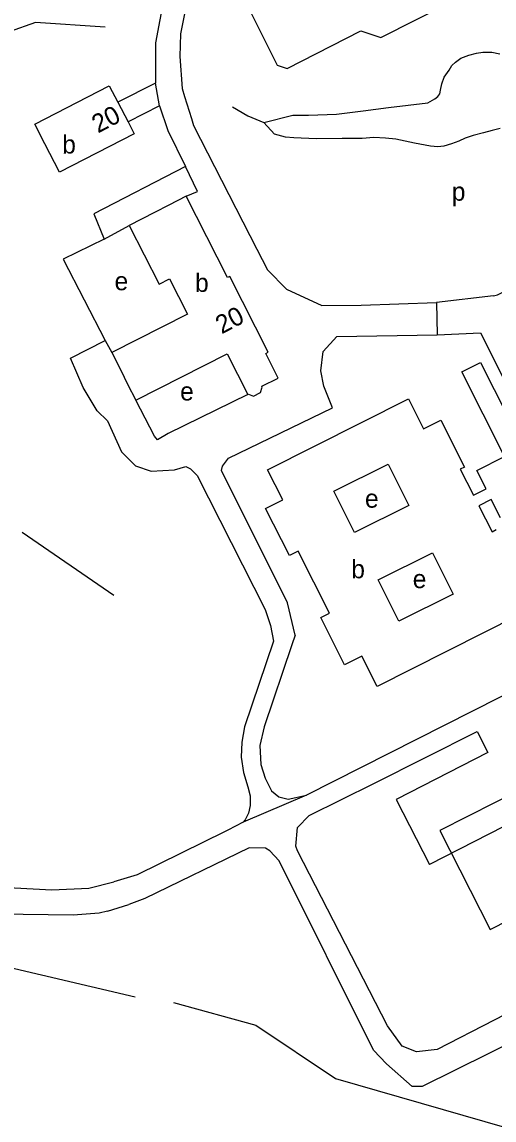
# Model space of a CAD drawing. Extents: x 158142 to 159655, y 385262 to 387204.
# Drawn here: x 158802.8 to 158905.5, y 386164.4 to 386403.5 of the extents above; entities that cross this region are included whole.
import ezdxf

# ---------------------------------------------------------------- set-up
doc = ezdxf.new("R2010")
doc.units = 0
for name, color, linetype in [('BLT_Basislijn', 7, 'Continuous'), ('BLT_Bebouwing', 7, 'Continuous'), ('BLT_Centroide', 7, 'Continuous'), ('BLT_Huisnummer', 7, 'Continuous'), ('BLT_Plantopo', 7, 'Continuous'), ('BLT_Vlakafsluiter', 7, 'Continuous')]:
    doc.layers.add(name, color=color, linetype=linetype)

msp = doc.modelspace()

# ---------------------------------------------------------------- linework, layer by layer
at = {"layer": 'BLT_Basislijn'}
for p, q in [((158851.89, 386406.97), (158858.34, 386394.06)), ((158831.88, 386390.19), (158823.68, 386386.01)), ((158832.78, 386385.23), (158831.88, 386390.19)), ((158838.18, 386387.27), (158839.69, 386382.43)), ((158832.78, 386385.23), (158825.9, 386381.7)), ((158820.68, 386356.19), (158826.18, 386359.19)), ((158820.95, 386334.15), (158822.37, 386331.49)), ((158819.17, 386318.8), (158816.15, 386323.91)), ((158802.88, 386292.41), (158822.8, 386278.65)), ((158862.25, 386269.97), (158861.53, 386267.84)), ((158857.51, 386268.65), (158851.23, 386250)), ((158861.53, 386267.84), (158855.51, 386250)), ((158901.79, 386248.97), (158904.15, 386244.37)), ((158904.15, 386244.37), (158884.21, 386234.14)), ((158934.79, 386242.24), (158891.45, 386220.02)), ((158864.7, 386235.1), (158850.97, 386229.24)), ((158884.21, 386234.14), (158891.45, 386220.02)), ((158850.97, 386229.24), (158847.58, 386227.51)), ((158821.41, 386209.88), (158826.08, 386211.28)), ((158784, 386201.42), (158827.48, 386191.22))]:
    msp.add_line(p, q, dxfattribs=at)
for points in [[(158858.34, 386394.06), (158860.47, 386393.36), (158876.54, 386401.57), (158880.9, 386400.07), (158949.09, 386434.63)], [(158843.29, 386430.77), (158837.33, 386400.92), (158837.2, 386395.94), (158837.65, 386388.99), (158838.18, 386387.27)], [(158836.62, 386424.04), (158831.91, 386398.97), (158831.88, 386390.19)], [(158820.92, 386402.37), (158805.76, 386403.38), (158800.05, 386401.35), (158789.96, 386389.69), (158788.28, 386379.99), (158783.8, 386372.81), (158785.38, 386364.31), (158786.18, 386360.05), (158771.15, 386323.25)], [(158906.8, 386380.3), (158905.07, 386379.85), (158903.18, 386379.34), (158900.98, 386378.79), (158899.22, 386378.16), (158897.83, 386377.53), (158896.22, 386376.92), (158894.54, 386376.46), (158893.24, 386376.27), (158891.64, 386376.41), (158888.2, 386377.1), (158884.11, 386377.96), (158881.92, 386378.2), (158879.37, 386378.33), (158876.8, 386378.14), (158872.5, 386378.08), (158866.83, 386378.01), (158861.94, 386378.24), (158860.14, 386378.41), (158857.76, 386379.05), (158855.42, 386381.62), (158861.72, 386383.19), (158865.15, 386383.21), (158871.2, 386383.4), (158877.05, 386384.1), (158882.55, 386384.87), (158891.06, 386385.9), (158892.59, 386386.73), (158893.28, 386387.27), (158893.68, 386387.84), (158893.85, 386388.62), (158894.16, 386390.03), (158894.66, 386391.44), (158895.73, 386393.02), (158896.32, 386393.97), (158897.14, 386394.75), (158898.3, 386395.59), (158900.01, 386396.24), (158901.67, 386396.68), (158903.06, 386396.92), (158904.98, 386396.94), (158906.76, 386396.58)], [(158905.37, 386343.81), (158906.21, 386344.08), (158977.73, 386380.2), (158991.61, 386387.46), (159005.32, 386393.92)], [(158832.78, 386385.23), (158834.58, 386379.83), (158838.41, 386372.01)], [(158848.62, 386384.98), (158851.98, 386383.07), (158855.42, 386381.62)], [(158839.69, 386382.43), (158840.15, 386380.94), (158853.91, 386354.02)], [(158838.41, 386372.01), (158818.43, 386361.7), (158820.68, 386356.19)], [(158838.56, 386365.53), (158841, 386366.54), (158838.41, 386372.01)], [(158820.68, 386356.19), (158811.79, 386351.81), (158820.95, 386334.15)], [(158853.91, 386354.02), (158856.22, 386349.54), (158860.35, 386345.29), (158868.06, 386341.71), (158876.57, 386341.82), (158892.95, 386342.41)], [(158905.37, 386343.81), (158892.95, 386342.41)], [(158816.15, 386323.91), (158813.38, 386330.3), (158820.95, 386334.15)], [(158862.25, 386269.97), (158860.58, 386276.98), (158846.22, 386305.84), (158846.43, 386306.76), (158847.78, 386308.49), (158870.37, 386319.43), (158868.45, 386324.2), (158867.81, 386327.54), (158868.34, 386331.76), (158871.29, 386335), (158893.14, 386335.34)], [(158893.14, 386335.34), (158902.56, 386335.77), (158931.06, 386279.11), (158933.07, 386275.16), (158933.19, 386272.61), (158932.37, 386270.21), (158930.86, 386268.67)], [(158851.97, 386322.36), (158834.61, 386313.88), (158832.32, 386312.51), (158831.65, 386313.27), (158827.59, 386321.1)], [(158819.17, 386318.8), (158821.43, 386316.63), (158824.47, 386309.84), (158827.49, 386306.84), (158830.93, 386305.65), (158836.01, 386305.94), (158838.45, 386306.65)], [(158838.45, 386306.65), (158839.47, 386306.18), (158840.91, 386304.74), (158855.71, 386275.53), (158856.86, 386272.09), (158857.51, 386268.65)], [(158930.86, 386268.67), (158876.59, 386241.13)], [(158851.23, 386250), (158850.63, 386246.68), (158850.47, 386243.38), (158851.01, 386240.01), (158851.98, 386236.9), (158852.48, 386234.95), (158852.48, 386232.86), (158852.13, 386231.22), (158851.39, 386229.74), (158850.97, 386229.24)], [(158855.51, 386250), (158854.56, 386245.95), (158854.75, 386241.79), (158855.7, 386238.84), (158857.11, 386236.09), (158858.71, 386234.73), (158860.74, 386234.23), (158864.7, 386235.1)], [(158917.92, 386192.49), (158893.11, 386179.72), (158888.65, 386179.21), (158885.54, 386180.45), (158882.29, 386184.86), (158862.76, 386223.01), (158862.41, 386223.98), (158862.73, 386228.05), (158865.28, 386230.66), (158879.32, 386237.64), (158901.79, 386248.97)], [(158766.75, 386242.48), (158773.99, 386219.91), (158775.65, 386217.36), (158777.55, 386216.46), (158778.19, 386216.19), (158809.3, 386214.52), (158817.41, 386214.84), (158822.79, 386216.21)], [(158876.59, 386241.13), (158864.7, 386235.1)], [(158847.58, 386227.51), (158847.04, 386227.18), (158827.9, 386217.78), (158822.79, 386216.21)], [(158918.97, 386186.13), (158889.83, 386171.69), (158887.7, 386171.69), (158882.12, 386176.58), (158879.27, 386179.61), (158858.76, 386220.8), (158856.77, 386222.98), (158855.81, 386223.55), (158852.24, 386223.62), (158829.59, 386212.59), (158826.08, 386211.28)], [(158821.41, 386209.88), (158819.62, 386209.45), (158813.97, 386208.96), (158781.24, 386209.43), (158779.93, 386209.28), (158778.74, 386208.13), (158778.55, 386207.06), (158786.18, 386184.09), (158790.63, 386166.67), (158791.76, 386162.26), (158793.56, 386152.97), (158797.45, 386127.33), (158798.64, 386111.47), (158799.12, 386093), (158890.75, 386114.16)], [(158835.8, 386189.99), (158853.7, 386185.02), (158871.01, 386173.44), (158922.15, 386158.65), (158927.01, 386155.08), (158945.44, 386129.76)]]:
    msp.add_lwpolyline(points, dxfattribs=at)
at = {"layer": 'BLT_Bebouwing'}
for p, q in [((158823.68, 386386.01), (158825.9, 386381.7)), ((158860.98, 386287.32), (158855.82, 386297.55))]:
    msp.add_line(p, q, dxfattribs=at)
for points in [[(158825.9, 386381.7), (158827.22, 386379.13), (158810.99, 386370.77), (158807.8, 386376.97), (158805.6, 386381.25), (158821.82, 386389.61), (158823.68, 386386.01)], [(158838.56, 386365.53), (158834.78, 386363.61), (158831.64, 386361.96), (158826.18, 386359.19)], [(158851.97, 386322.36), (158852.13, 386322.44), (158853.22, 386322.01), (158854.7, 386322.77), (158855.08, 386323.94), (158854.98, 386324.14), (158858.56, 386325.9), (158855.89, 386331.32), (158856.39, 386331.57), (158848.02, 386348.08), (158847.51, 386347.83), (158838.56, 386365.53)], [(158826.18, 386359.19), (158832.68, 386346.41), (158834.91, 386347.54), (158838.82, 386339.86), (158822.37, 386331.49)], [(158822.37, 386331.49), (158824.31, 386327.67), (158825.78, 386324.64), (158827.59, 386321.1)], [(158827.59, 386321.1), (158847.47, 386331.21), (158851.97, 386322.36)], [(158855.82, 386297.55), (158859.56, 386299.43), (158856.26, 386305.98), (158886.87, 386321.42), (158890.18, 386314.85), (158893.93, 386316.74), (158899.08, 386306.53), (158898.16, 386306.07), (158901.02, 386300.42), (158903.77, 386301.81), (158901.74, 386305.82), (158907.76, 386308.86), (158898.47, 386327.27), (158902.57, 386329.34), (158926.37, 386282.18)], [(158906.93, 386295.47), (158904.9, 386299.49), (158902.2, 386298.13), (158905.05, 386292.48), (158905.94, 386292.93)], [(158910.67, 386274.26), (158880.05, 386258.81), (158876.74, 386265.38), (158872.99, 386263.49), (158867.81, 386273.78), (158869.73, 386274.75), (158862.9, 386288.28), (158860.98, 386287.32)]]:
    msp.add_lwpolyline(points, dxfattribs=at)
for points in [[(158870.68, 386301.33), (158882.46, 386307.19), (158886.94, 386298.2), (158875.16, 386292.33)], [(158880.31, 386281.98), (158892.09, 386287.85), (158896.57, 386278.87), (158884.79, 386273)]]:
    msp.add_lwpolyline(points, close=True, dxfattribs=at)
at = {"layer": 'BLT_Plantopo'}
msp.add_lwpolyline([(158929.96, 386243.43), (158912.69, 386234.65), (158911.72, 386236.55), (158893.69, 386227.38), (158904.65, 386205.84), (158924.75, 386216.06), (158925.78, 386214.04), (158940.98, 386221.77)], close=True, dxfattribs=at)
at = {"layer": 'BLT_Vlakafsluiter'}
msp.add_line((158892.95, 386342.41), (158893.14, 386335.34), dxfattribs=at)

# ---------------------------------------------------------------- texts
at = {"layer": 'BLT_Centroide'}
for s, p in [('b', (158811.59, 386374.83)), ('p', (158896.3, 386364.56)), ('b', (158840.47, 386344.7)), ('e', (158822.97, 386345.06)), ('e', (158837.23, 386321.06)), ('e', (158877.43, 386297.71)), ('b', (158874.44, 386282.34)), ('e', (158887.81, 386280.2))]:
    msp.add_text(s, height=4, dxfattribs=at).set_placement(p)
at = {"layer": 'BLT_Huisnummer'}
for p in [(158819.37, 386379.18), (158846.27, 386335.44)]:
    msp.add_text('20', height=4, rotation=27.8253, dxfattribs=at).set_placement(p)

doc.saveas('drawing.dxf')
